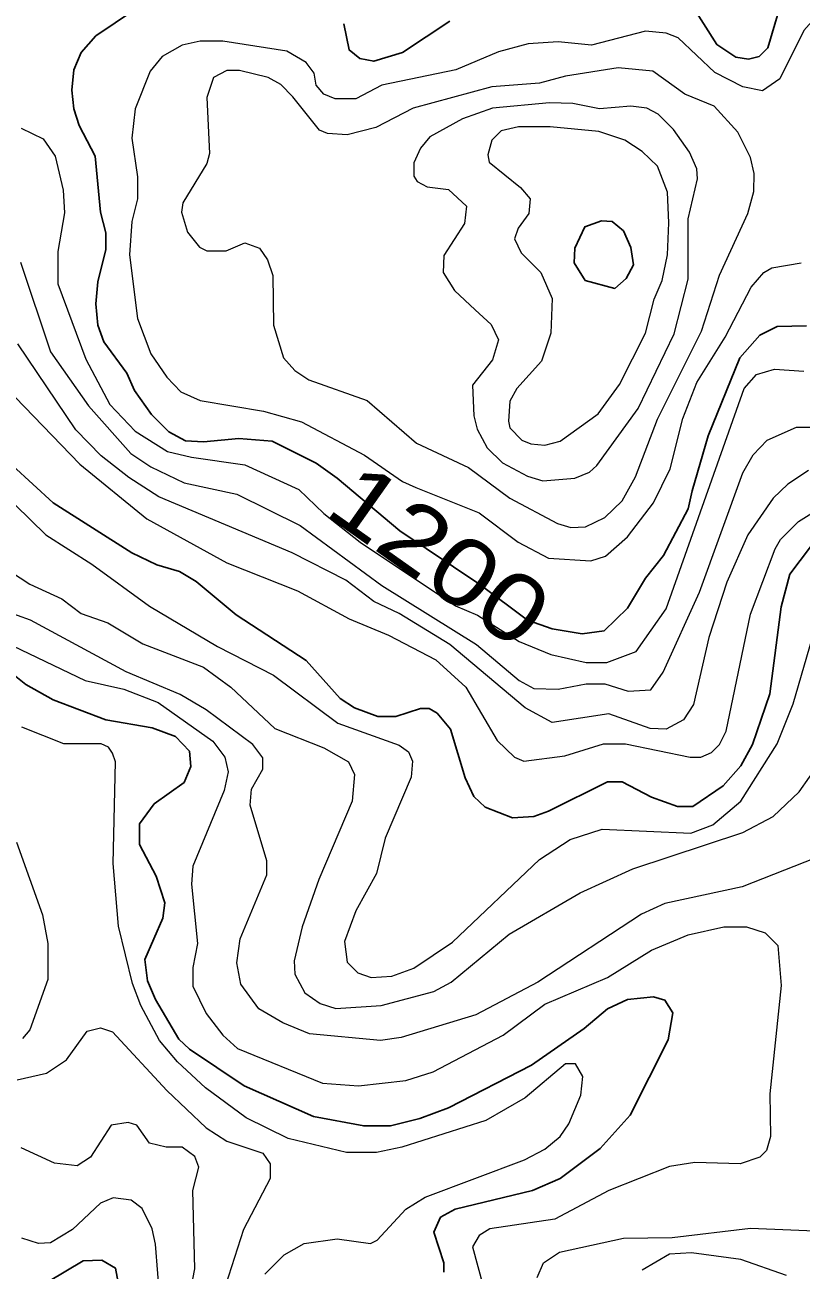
# Model space of a CAD drawing. Extents: x 577 to 602.9, y 7483.8 to 7511.6.
# Drawn here: x 583.765 to 584.69, y 7486.258 to 7487.741 of the extents above; entities that cross this region are included whole.
import ezdxf
from ezdxf.enums import TextEntityAlignment as Align

# ---------------------------------------------------------------- set-up
doc = ezdxf.new("R2010")
doc.units = 0
doc.header["$LTSCALE"] = 0.032
doc.layers.add('1', color=7, linetype='Continuous', lineweight=25)
doc.layers.add('2', color=7, linetype='Continuous', lineweight=13)
doc.layers.add('61', color=7, linetype='Continuous')

msp = doc.modelspace()

# ---------------------------------------------------------------- linework, layer by layer
at = {"layer": '1'}
for points in [[(584.5576, 7487.7676), (584.5894, 7487.7175), (584.6117, 7487.7024), (584.6268, 7487.7), (584.6395, 7487.7032), (584.6498, 7487.7135), (584.6697, 7487.7811)], [(584.56, 7487.1863), (584.5552, 7487.1648), (584.5258, 7487.1092), (584.5043, 7487.0821), (584.4829, 7487.0464), (584.455, 7487.0193), (584.4288, 7487.0161), (584.393, 7487.0217), (584.3636, 7487.032), (584.3072, 7487.0748), (584.2116, 7487.1386), (584.1373, 7487.2013), (584.112, 7487.219), (584.0598, 7487.2452), (584.0201, 7487.2483), (583.9779, 7487.2444), (583.9565, 7487.2459), (583.9366, 7487.2563), (583.9159, 7487.277), (583.896, 7487.3056), (583.8865, 7487.3263), (583.8594, 7487.3636), (583.8523, 7487.3835), (583.8499, 7487.409), (583.8523, 7487.4352), (583.8618, 7487.4734), (583.8618, 7487.4932), (583.8555, 7487.5179), (583.8491, 7487.5847), (583.83, 7487.6213), (583.8237, 7487.6411), (583.8213, 7487.6634), (583.8237, 7487.6873), (583.8324, 7487.7079), (583.8499, 7487.7278), (583.896, 7487.7588)], [(584.1449, 7487.7421), (584.1513, 7487.7111), (584.164, 7487.7008), (584.1807, 7487.6976), (584.2149, 7487.7079), (584.2713, 7487.7453)], [(584.696, 7487.3827), (584.661, 7487.3819), (584.6403, 7487.3716), (584.6165, 7487.3445), (584.5791, 7487.2515), (584.56, 7487.1863)], [(583.9692, 7487.0782), (583.9493, 7487.0901), (583.9223, 7487.098), (583.8928, 7487.1124), (583.799, 7487.172), (583.7505, 7487.2165)], [(584.7007, 7487.1195), (584.6761, 7487.0869), (584.6658, 7487.0479), (584.6522, 7486.9446), (584.6316, 7486.8841), (584.618, 7486.8587), (584.5966, 7486.8348), (584.5608, 7486.8102), (584.5425, 7486.8102), (584.5115, 7486.8213), (584.4765, 7486.8396), (584.459, 7486.8396), (584.389, 7486.8046), (584.3715, 7486.7983), (584.3461, 7486.7967), (584.3135, 7486.8094), (584.3, 7486.8221), (584.2896, 7486.8444), (584.2721, 7486.9024), (584.2562, 7486.9215), (584.2467, 7486.9271), (584.2364, 7486.9271), (584.2069, 7486.9175), (584.1855, 7486.9175), (584.1576, 7486.9279), (584.1409, 7486.939), (584.1004, 7486.9843), (584.0169, 7487.0384), (583.9692, 7487.0782)], [(583.7322, 7486.9827), (583.7664, 7486.9557), (583.799, 7486.9374), (583.8618, 7486.9136), (583.9167, 7486.904), (583.9445, 7486.8937), (583.9612, 7486.8762), (583.9628, 7486.8579), (583.9549, 7486.8388), (583.9191, 7486.8134), (583.9016, 7486.7895), (583.9016, 7486.7649), (583.9215, 7486.7275), (583.9318, 7486.6957), (583.9294, 7486.6774), (583.908, 7486.6281), (583.9111, 7486.6026), (583.9207, 7486.5804), (583.9485, 7486.5335), (583.9612, 7486.5215), (584.0264, 7486.4778), (584.1091, 7486.4412), (584.1688, 7486.4301), (584.2006, 7486.4301), (584.2356, 7486.4388), (584.2698, 7486.4516), (584.3684, 7486.5025), (584.4312, 7486.5462), (584.459, 7486.5693), (584.4829, 7486.5804), (584.5139, 7486.5836), (584.5274, 7486.5796), (584.5369, 7486.5645), (584.5314, 7486.5327), (584.486, 7486.4428), (584.4503, 7486.4031), (584.4025, 7486.3673), (584.3699, 7486.353), (584.2777, 7486.3307), (584.2602, 7486.3212), (584.2523, 7486.3037), (584.2642, 7486.2671), (584.2642, 7486.256)], [(583.8785, 7486.2329), (583.873, 7486.2607), (583.8571, 7486.2703), (583.8348, 7486.2695), (583.7934, 7486.2448)]]:
    msp.add_lwpolyline(points, dxfattribs=at)
msp.add_lwpolyline([(584.4324, 7487.4366), (584.4678, 7487.4272), (584.4813, 7487.4392), (584.49, 7487.4551), (584.4868, 7487.4758), (584.4781, 7487.4956), (584.4646, 7487.5068), (584.4519, 7487.5076), (584.432, 7487.5004), (584.42, 7487.475), (584.4192, 7487.4575)], close=True, dxfattribs=at)
at = {"layer": '2'}
for points in [[(584.7119, 7487.7557), (584.6928, 7487.7342), (584.6642, 7487.6769), (584.6435, 7487.6626), (584.6204, 7487.6674), (584.587, 7487.6841), (584.5433, 7487.7254), (584.529, 7487.731), (584.5043, 7487.7334), (584.4399, 7487.7167), (584.4002, 7487.7207), (584.3644, 7487.7183), (584.3294, 7487.7087), (584.2785, 7487.6873), (584.1902, 7487.669), (584.1592, 7487.6531), (584.1346, 7487.6531), (584.1211, 7487.6586), (584.1123, 7487.669), (584.1099, 7487.6833), (584.1004, 7487.696), (584.0773, 7487.7095), (584.001, 7487.7215), (583.9739, 7487.7215)], [(583.9739, 7487.7215), (583.9525, 7487.7167), (583.9286, 7487.7032), (583.9143, 7487.6857), (583.8968, 7487.6411), (583.8928, 7487.6062), (583.8992, 7487.56), (583.8992, 7487.5338), (583.8928, 7487.5068), (583.8897, 7487.467), (583.8992, 7487.3915), (583.9151, 7487.3493), (583.9342, 7487.3215), (583.9509, 7487.304), (583.9739, 7487.2937), (584.0495, 7487.2809), (584.0948, 7487.2682), (584.1696, 7487.2285), (584.2149, 7487.1974), (584.2308, 7487.1903)], [(583.7608, 7487.6181), (583.7871, 7487.6054), (583.8014, 7487.5847), (583.8109, 7487.5441), (583.8125, 7487.5171), (583.8046, 7487.471), (583.8046, 7487.4328), (583.838, 7487.343), (583.8666, 7487.2889), (583.8968, 7487.2571), (583.935, 7487.2332), (583.9636, 7487.2261), (584.0272, 7487.2173), (584.0916, 7487.1879), (584.1213, 7487.1591), (584.1647, 7487.125), (584.278, 7487.0493), (584.3041, 7487.0383), (584.354, 7487.0066), (584.3914, 7486.9915), (584.4336, 7486.9819), (584.4582, 7486.9819), (584.4932, 7486.9947), (584.529, 7487.0456)], [(583.76, 7487.4583), (583.7958, 7487.3517), (583.8412, 7487.2873), (583.8913, 7487.2308), (583.9151, 7487.2149), (583.9549, 7487.1958), (584.0177, 7487.1823), (584.0932, 7487.145), (584.1902, 7487.0734), (584.3032, 7487.0034), (584.354, 7486.9605), (584.3715, 7486.9509), (584.4002, 7486.9501), (584.4336, 7486.9565)], [(584.2308, 7487.1903), (584.3063, 7487.1601), (584.3525, 7487.1251), (584.389, 7487.106), (584.4391, 7487.1028), (584.4566, 7487.1084), (584.4829, 7487.1314), (584.5139, 7487.172), (584.5338, 7487.2125), (584.5489, 7487.2722), (584.5656, 7487.3151), (584.599, 7487.3692), (584.63, 7487.4288), (584.6451, 7487.4463), (584.6546, 7487.4519), (584.6896, 7487.4575)], [(584.1807, 7487.0543), (584.1473, 7487.0798), (584.0837, 7487.1124), (583.9246, 7487.1792), (583.8889, 7487.2022), (583.8563, 7487.2277), (583.826, 7487.2587), (583.7569, 7487.3612)], [(584.529, 7487.0456), (584.622, 7487.308), (584.6363, 7487.3247), (584.6578, 7487.331), (584.6928, 7487.3286)], [(583.7537, 7487.2976), (583.8308, 7487.2181), (583.9103, 7487.1529), (584.0058, 7487.1004), (584.09, 7487.067), (584.1513, 7487.0336), (584.1982, 7487.0145), (584.2546, 7486.9851), (584.2904, 7486.9525), (584.3278, 7486.8889), (584.3485, 7486.869), (584.3596, 7486.8643), (584.4081, 7486.8706), (584.4542, 7486.8849), (584.4805, 7486.8849), (584.5576, 7486.869), (584.5703, 7486.869), (584.5831, 7486.8746), (584.5926, 7486.8841), (584.6005, 7486.9), (584.6292, 7487.0392), (584.6586, 7487.1171), (584.665, 7487.1283), (584.6864, 7487.1497), (584.7182, 7487.1696)], [(584.4336, 7486.9565), (584.4558, 7486.9565), (584.4837, 7486.9478), (584.5107, 7486.9491), (584.5252, 7486.9702), (584.5687, 7487.0654), (584.6204, 7487.2078), (584.6324, 7487.2292), (584.6491, 7487.2467), (584.684, 7487.2618), (584.7095, 7487.2618)], [(584.6984, 7487.2102), (584.6737, 7487.1943), (584.6562, 7487.1776), (584.626, 7487.1338), (584.6013, 7487.0774), (584.5799, 7487.0114), (584.5616, 7486.9319), (584.5497, 7486.9136), (584.529, 7486.9024), (584.5099, 7486.9032), (584.4606, 7486.9207), (584.393, 7486.9104), (584.3612, 7486.9279), (584.2713, 7487.0034), (584.2109, 7487.04), (584.1807, 7487.0543)], [(583.7537, 7487.1696), (583.7903, 7487.1338), (583.8451, 7487.0988), (583.9135, 7487.0487), (583.9946, 7487.001), (584.0614, 7486.9668), (584.1378, 7486.9096), (584.2109, 7486.8833), (584.222, 7486.8754), (584.2268, 7486.8643), (584.2252, 7486.8452), (584.1942, 7486.7728), (584.1839, 7486.7307), (584.1592, 7486.6861), (584.1457, 7486.6496), (584.1489, 7486.6249), (584.1616, 7486.6122), (584.1775, 7486.6066), (584.2022, 7486.6082), (584.2284, 7486.6178), (584.2745, 7486.6488), (584.3779, 7486.7474), (584.4145, 7486.7712), (584.4526, 7486.7832), (584.5584, 7486.7784), (584.5846, 7486.7887), (584.618, 7486.8166), (584.661, 7486.8849), (584.6801, 7486.9326), (584.7063, 7487.0225)], [(583.7481, 7487.0901), (583.7712, 7487.075), (583.8093, 7487.0575), (583.8324, 7487.04), (583.8642, 7487.0289), (583.9056, 7487.0042), (583.9779, 7486.9764), (584.0105, 7486.9525), (584.063, 7486.9032), (584.1211, 7486.8802), (584.1505, 7486.8635), (584.1576, 7486.8484), (584.1552, 7486.8166), (584.1155, 7486.7235), (584.0956, 7486.6671), (584.0861, 7486.6265), (584.0869, 7486.6106), (584.0988, 7486.5883), (584.1171, 7486.5756), (584.1354, 7486.57), (584.1894, 7486.5732), (584.2523, 7486.5899), (584.2729, 7486.6011), (584.3421, 7486.6583), (584.4264, 7486.7076), (584.4892, 7486.7362), (584.6204, 7486.7792), (584.6562, 7486.7983), (584.6872, 7486.8277), (584.7119, 7486.8627)], [(584.7818, 7486.7784), (584.6196, 7486.7148), (584.5274, 7486.6949), (584.4996, 7486.6822), (584.3763, 7486.6011), (584.3024, 7486.5621), (584.2133, 7486.5351), (584.1886, 7486.5319), (584.1044, 7486.5398), (584.0726, 7486.5526), (584.0439, 7486.5693), (584.0225, 7486.5987), (584.0177, 7486.6241), (584.0217, 7486.6527), (584.0535, 7486.7291), (584.0535, 7486.7458), (584.0336, 7486.8118), (584.0352, 7486.8309), (584.0487, 7486.8547), (584.0487, 7486.8682), (584.0368, 7486.8841), (583.9811, 7486.9255), (583.9501, 7486.9438), (583.8857, 7486.9708), (583.772, 7487.032), (583.741, 7487.0432)], [(583.7314, 7487.0106), (583.8372, 7486.9605), (583.8833, 7486.9501), (583.9239, 7486.9342), (583.9891, 7486.8881), (584.0034, 7486.869), (584.0073, 7486.8515), (584.0026, 7486.8293), (583.9652, 7486.7394), (583.9636, 7486.7179), (583.9708, 7486.6472), (583.9652, 7486.6186), (583.9652, 7486.5963), (583.9811, 7486.5637), (584.001, 7486.5382), (584.0185, 7486.5223), (584.1195, 7486.481), (584.1624, 7486.4778), (584.2189, 7486.4842), (584.2515, 7486.4945), (584.335, 7486.5382), (584.3843, 7486.5748), (584.459, 7486.6066), (584.5115, 7486.6392), (584.5552, 7486.6575), (584.5974, 7486.6671), (584.6244, 7486.6671), (584.6467, 7486.6599), (584.6618, 7486.6448), (584.6658, 7486.5971), (584.6522, 7486.4683), (584.653, 7486.4174), (584.6483, 7486.4007), (584.6403, 7486.3927), (584.6172, 7486.3848), (584.5632, 7486.3864), (584.533, 7486.3816), (584.4606, 7486.353), (584.3962, 7486.3188), (584.3191, 7486.3076), (584.3063, 7486.2997), (584.2984, 7486.2862), (584.3111, 7486.2393)], [(584.0511, 7486.2536), (584.0741, 7486.2766), (584.098, 7486.2901), (584.137, 7486.2957), (584.1767, 7486.2901), (584.1847, 7486.2941), (584.2189, 7486.3307), (584.2419, 7486.345), (584.3604, 7486.3895), (584.3843, 7486.4023), (584.4025, 7486.4174), (584.4129, 7486.4325), (584.4272, 7486.4667), (584.4296, 7486.4889), (584.4208, 7486.504), (584.4089, 7486.504), (584.3612, 7486.4635), (584.3143, 7486.4365), (584.2141, 7486.4046), (584.1839, 7486.3983), (584.1481, 7486.3983), (584.0789, 7486.415), (584.0288, 7486.4396), (583.9803, 7486.4754), (583.9469, 7486.5064), (583.9254, 7486.5319), (583.9032, 7486.5732), (583.8936, 7486.5995), (583.8769, 7486.6679), (583.8706, 7486.7426), (583.873, 7486.8635), (583.8698, 7486.8738), (583.865, 7486.881), (583.8563, 7486.8849), (583.8117, 7486.8849), (583.7616, 7486.9048)], [(583.7553, 7486.768), (583.7863, 7486.6814), (583.7926, 7486.6472), (583.7926, 7486.6042), (583.7712, 7486.5446), (583.7624, 7486.5343)], [(583.7561, 7486.485), (583.7911, 7486.4929), (583.8149, 7486.5088), (583.8396, 7486.543), (583.8555, 7486.547), (583.8698, 7486.5422), (583.9342, 7486.4722), (583.9811, 7486.4277), (584.0058, 7486.4118), (584.0487, 7486.3975), (584.0574, 7486.3848), (584.0574, 7486.3673), (584.0256, 7486.3068), (583.997, 7486.2178)], [(583.9517, 7486.178), (583.9676, 7486.2599), (583.9652, 7486.353), (583.9724, 7486.3808), (583.9676, 7486.3935), (583.9525, 7486.4046), (583.9334, 7486.4046), (583.9135, 7486.4094), (583.8984, 7486.4309), (583.8881, 7486.4341), (583.8682, 7486.4309), (583.8435, 7486.3927), (583.8276, 7486.3824), (583.8006, 7486.3856), (583.7608, 7486.4039)], [(583.9262, 7486.2194), (583.9207, 7486.2893), (583.9167, 7486.3076), (583.9048, 7486.3315), (583.892, 7486.3418), (583.8706, 7486.3442), (583.8555, 7486.3379), (583.8221, 7486.3068), (583.7958, 7486.2909), (583.7815, 7486.2901), (583.7616, 7486.2965)], [(584.3755, 7486.2496), (584.3827, 7486.2671), (584.4018, 7486.2798), (584.4781, 7486.2965), (584.5361, 7486.2973), (584.6292, 7486.3084), (584.7254, 7486.3045)], [(584.6721, 7486.252), (584.618, 7486.2711), (584.5592, 7486.279), (584.533, 7486.2774), (584.5004, 7486.2583)]]:
    msp.add_lwpolyline(points, dxfattribs=at)
for points in [[(584.1727, 7487.2937), (584.2316, 7487.2428), (584.2936, 7487.2141), (584.3429, 7487.1776), (584.3994, 7487.1473), (584.4153, 7487.1426), (584.4328, 7487.1434), (584.4558, 7487.1545), (584.4765, 7487.1744), (584.4924, 7487.203), (584.5186, 7487.2714), (584.5711, 7487.3764), (584.5926, 7487.4431), (584.626, 7487.5163), (584.6332, 7487.5425), (584.6339, 7487.564), (584.6292, 7487.5831), (584.6141, 7487.6133), (584.5862, 7487.6443), (584.5512, 7487.6586), (584.5131, 7487.6857), (584.4717, 7487.6897), (584.4089, 7487.6801), (584.3779, 7487.6714), (584.3214, 7487.6674), (584.2276, 7487.6419), (584.1831, 7487.6189), (584.1489, 7487.6101), (584.1258, 7487.6117), (584.1163, 7487.6157), (584.0845, 7487.6555), (584.0702, 7487.6698), (584.0551, 7487.6785), (584.0209, 7487.6865), (584.0058, 7487.6865), (583.9899, 7487.6785), (583.9819, 7487.6547), (583.9851, 7487.5879), (583.9819, 7487.5759), (583.9533, 7487.529), (583.9517, 7487.5179), (583.9588, 7487.494), (583.9732, 7487.4765), (583.9819, 7487.4718), (584.005, 7487.4718), (584.0272, 7487.4813), (584.0447, 7487.475), (584.0543, 7487.4614), (584.0606, 7487.4424), (584.0614, 7487.3835), (584.0733, 7487.3445), (584.0869, 7487.3294), (584.1036, 7487.3183)], [(584.3016, 7487.4018), (584.3206, 7487.3843), (584.3294, 7487.366), (584.3222, 7487.3422), (584.2984, 7487.3119), (584.3, 7487.2754), (584.3039, 7487.2595), (584.3159, 7487.2372), (584.3342, 7487.2197), (584.3636, 7487.2038), (584.3819, 7487.1982), (584.42, 7487.2014), (584.4375, 7487.2086), (584.4463, 7487.2165), (584.4956, 7487.2841), (584.5385, 7487.3732), (584.5552, 7487.4384), (584.5552, 7487.5099), (584.5664, 7487.5577), (584.5656, 7487.5696), (584.5568, 7487.5895), (584.5377, 7487.6165), (584.5194, 7487.6348), (584.5059, 7487.6419), (584.4868, 7487.6443), (584.4495, 7487.6411), (584.4177, 7487.6475), (584.3898, 7487.6483), (584.3222, 7487.6419), (584.2865, 7487.6292), (584.2475, 7487.6078), (584.2364, 7487.5942), (584.2284, 7487.5767), (584.2284, 7487.5608), (584.2324, 7487.5545), (584.2443, 7487.5481), (584.2698, 7487.5449), (584.2912, 7487.5251), (584.2888, 7487.5044), (584.2642, 7487.4662), (584.2634, 7487.4463), (584.2769, 7487.4249)], [(584.3795, 7487.4463), (584.393, 7487.4153), (584.3914, 7487.374), (584.3803, 7487.3406), (584.3509, 7487.308), (584.3429, 7487.2929), (584.3413, 7487.269), (584.3429, 7487.2611), (584.3572, 7487.2467), (584.3676, 7487.242), (584.3843, 7487.2404), (584.4025, 7487.2452), (584.4479, 7487.2778), (584.4733, 7487.3127), (584.5043, 7487.374), (584.5147, 7487.4145), (584.5242, 7487.4368), (584.5306, 7487.467), (584.5322, 7487.5052), (584.5306, 7487.5418), (584.5186, 7487.5728), (584.5004, 7487.5903), (584.4797, 7487.6038), (584.4487, 7487.6141), (584.3906, 7487.6197), (584.3532, 7487.6197), (584.3326, 7487.6149), (584.3214, 7487.6038), (584.3167, 7487.5863), (584.3183, 7487.5775), (584.3556, 7487.5473), (584.3668, 7487.5338), (584.3652, 7487.5163), (584.3525, 7487.4988), (584.3485, 7487.4861), (584.3564, 7487.4694)]]:
    msp.add_lwpolyline(points, close=True, dxfattribs=at)

# ---------------------------------------------------------------- texts
at = {"layer": '61', "width": 1.2}
msp.add_text('1200', height=0.08, rotation=324.736, dxfattribs=at).set_placement((584.2365, 7487.077), align=Align.CENTER)

doc.saveas('drawing.dxf')
